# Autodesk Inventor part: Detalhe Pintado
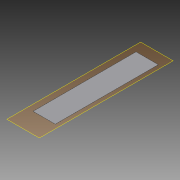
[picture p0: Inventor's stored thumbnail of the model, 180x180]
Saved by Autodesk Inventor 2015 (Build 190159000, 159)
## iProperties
Created: 2015-04
Part Number: Detalhe Pintado
Material: Generic
Document SubType Name: Modeling
Designer: suporte
Density: 1 g/cm^3
Appearance: Default
Author: suporte
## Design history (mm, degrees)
workplane "Work Plane1"
sketch "Sketch1"
  geometry: L1 (81.358, 2019.098)-(466.358, 2019.098); L2 (466.358, 2019.098)-(466.358, 239.098); L3 (466.358, 239.098)-(81.358, 239.098); L4 (81.358, 239.098)-(81.358, 2019.098); 1 further point
  constraints: 8 end point, 2 parallel, 1 horizontal, 1 perpendicular
  dimensions: "d0" = 385 distance of L2.end L3.end; "d1" = 1780 distance of L1.end L2.end
extrude "Extrusion1" new body sketch "Sketch1" distance "d2" = 1; taper "d3" = 0 deg
body "Solid1"
